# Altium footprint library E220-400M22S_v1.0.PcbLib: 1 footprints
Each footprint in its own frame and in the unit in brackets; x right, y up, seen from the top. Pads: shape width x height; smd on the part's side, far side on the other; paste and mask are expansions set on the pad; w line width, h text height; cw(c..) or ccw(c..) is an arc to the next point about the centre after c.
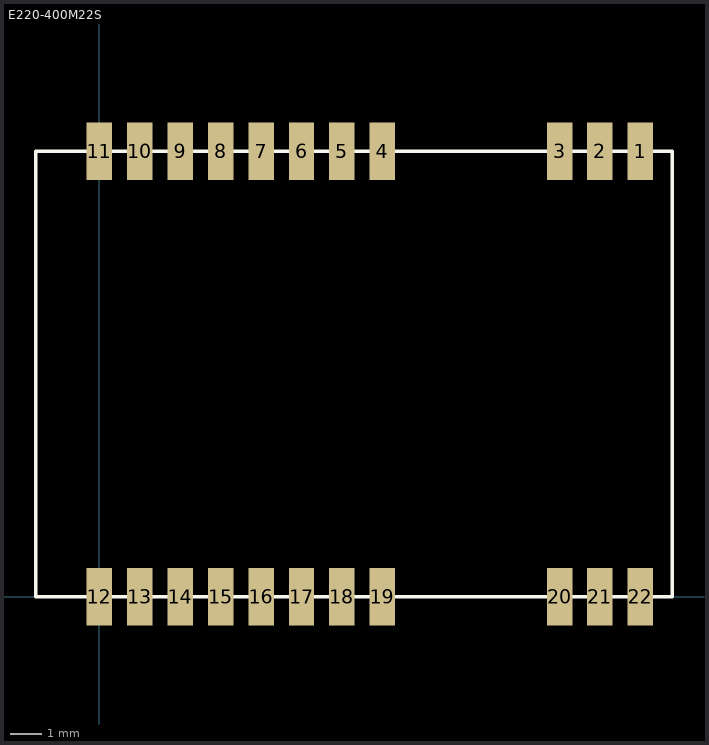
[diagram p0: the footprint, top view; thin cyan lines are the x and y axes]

## E220-400M22S [mm]
pads (22):
  rect 0.8x1.8 smd: 1(17,14) 2(15.73,14) 3(14.46,14) 4(8.89,14) 5(7.62,14) 6(6.35,14) 7(5.08,14) 8(3.81,14) 9(2.54,14) 10(1.27,14) 11(0,14) 12(0,0) 13(1.27,0) 14(2.54,0) 15(3.81,0) 16(5.08,0) 17(6.35,0) 18(7.62,0) 19(8.89,0) 20(14.46,0) 21(15.73,0) 22(17,0)
Top Overlay:
  lines w0.1: -2,0 18,0 18,14 -2,14 -2,0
